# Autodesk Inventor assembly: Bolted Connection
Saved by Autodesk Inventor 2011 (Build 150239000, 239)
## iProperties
Created: 2020-12
Part Number: Bolted Connection
Document SubType Name: Assembly
Designer: PC
ClientObjectVersion: 1
Author: PC
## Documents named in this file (3)
- C:\Users\PC\Documents\Inventor\workshop-crane-powered-by-drill\estructura-principal\Design Accelerator\Bolted Connection2.iam
- C:\Users\PC\Documents\Inventor\Content Center Files\R2011\en-US\DIN 931-1\DIN 931-1 - M14 x 55.ipt
- C:\Users\PC\Documents\Inventor\Content Center Files\R2011\en-US\DIN 555\DIN 555-5 - M14.ipt
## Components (2 placed, 2 different names)
1. DIN 931-1 - replaced by DIN EN 24014 M14 x 55:1
2. DIN 555 - replaced by DIN EN 24034 M14:1
